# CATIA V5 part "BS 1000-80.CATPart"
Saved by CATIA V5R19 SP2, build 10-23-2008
Part number: BS 1000-80
Bounding box of the stored display mesh (mm): x -24.865 to 24.865, y -24.997 to 24.997, z 0 to 198
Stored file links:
  C:\Users\Bora\Desktop\3D Katı model\BS serisi\BS 1000\BS 1000-80.CATPart
  C:\Program Files\Dassault Systemes\B19\intel_a\reffiles\standard\MetricThickPitch.txt
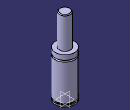
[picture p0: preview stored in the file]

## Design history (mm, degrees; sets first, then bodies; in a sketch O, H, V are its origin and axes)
Body1 (main body)
  Sketch1 on yz-plane, origin (0, 0, 0), H (0, 1, 0), V (0, 0, 1)
    point P2 (14, 196)
    line L1 (14, 196) -> (14, 117)
    point P3 (25, 104.5)
    line L2 (25, 117) -> (25, 104.5)
    point P6 (25, 100.5)
    line L3 (25, 100.5) -> (25, 7.5)
    line L4 (25, 4) -> (25, 0)
    point P9 (25, 100.5)
    point P10 (25, 104.5)
    arc A1 centre (25, 102.5) radius 2 from (25, 104.5) to (25, 100.5) ccw
    point P12 (14, 196)
    arc A2 centre (12, 196) radius 2 from (14, 196) to (12, 198) ccw
    point P13 (22.5, 4)
    point P14 (22.5, 4)
    line L5 (22.5, 7.5) -> (22.5, 4)
    line L6 (12, 198) -> (0, 198)
    point P16 (0, 198)
    line L7 (14, 117) -> (25, 117)
    line L8 (0, 0) -> (25, 0)
    line L9 (22.5, 7.5) -> (25, 7.5)
    line L10 (22.5, 4) -> (25, 4)
    coincidence: P16 V, P2 P12, P3 P10, P6 P9, P13 P14
    tangency: L6 A2
    horizontal: L7 H, L8 H, L9 H, L10 H
  Shaft1: profile Sketch1, axis Sketch1.V, angle 360
  Sketch2 on face of Shaft1 from Sketch1.L8, origin (0, 0, 0), H (1, 0, 0), V (0, -1, 0)
    point P1 (10, 0)
    distance P1 V = 10
  Hole1: placed by Sketch2, at (10, 0, 0) direction (0, 0, 1), diameter 6.647, depth 6, threaded "M8", thread diameter 8, thread depth 6, pitch 1.25
  CircPattern1: of Hole1, instances 2, angular step 180, axis from xy-plane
